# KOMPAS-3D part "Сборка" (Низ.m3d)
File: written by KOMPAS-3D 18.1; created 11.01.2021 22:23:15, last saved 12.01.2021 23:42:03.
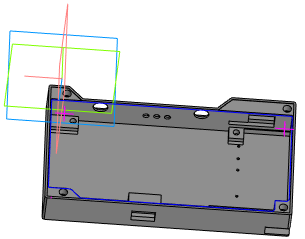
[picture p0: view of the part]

Document properties: Автор: DiSlord; Полное имя файла: Низ.m3d

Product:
- Part/product: Сборка
    Масса: 0.17294
  - Component [detail]: Деталь  | source file: Крышка экрана.m3d
  - Component [detail]: Низ  | source file: C:\Users\DiSlord\Documents\Низ.m3d

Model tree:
1. Эскиз:1  (with: Элемент выдавливания:1)
2. Элемент выдавливания:1
     Расстояние 1 = 17
3. Контур:1  (with: Элемент выдавливания:1)
     Радиус = 5
4. Элемент выдавливания:2  (with: Элемент выдавливания:1)
     Расстояние 2 = 15
5. Контур:2  (with: Элемент выдавливания:1)
     Радиус = 5
6. Элемент выдавливания:3  (with: Элемент выдавливания:1)
     Расстояние 2 = 15
7. Элемент выдавливания:4  (with: Элемент выдавливания:1)
     Расстояние 2 = 15
8. Элемент выдавливания:5  (with: Элемент выдавливания:1)
     Расстояние 2 = 15
9. Эскиз:2  (with: Элемент выдавливания:1)
10. Элемент выдавливания:6
     Расстояние 2 = 115
11. Эскиз:3  (with: Элемент выдавливания:1)
12. Элемент выдавливания:8
     Расстояние 2 = 17
13. Эскиз:4  (with: Элемент выдавливания:1, Элемент выдавливания:8)
14. Элемент выдавливания:9
     Расстояние 2 = 16
15. Эскиз:5  (with: Элемент выдавливания:9, Элемент выдавливания:1)
16. Эскиз:6  (with: Элемент выдавливания:1, Элемент выдавливания:9)
17. Элемент выдавливания:10  (with: Элемент выдавливания:1)
     Расстояние 1 = -17
18. Эскиз:7  (with: Элемент выдавливания:1, Элемент выдавливания:9, Элемент выдавливания:10)
19. Элемент выдавливания:11  (with: Элемент выдавливания:9)
     Расстояние 2 = 16
20. Эскиз:8  (with: Элемент выдавливания:9, Элемент выдавливания:11)
21. Элемент выдавливания:12
     Расстояние 1 = 0.01
22. Эскиз:9  (with: Элемент выдавливания:1, Элемент выдавливания:9)
23. Элемент выдавливания:13  (with: Элемент выдавливания:12)
     Расстояние 2 = 15.99
24. Эскиз:10  (with: Элемент выдавливания:12)
25. Элемент выдавливания:14
     Расстояние 2 = 1.01
26. Эскиз:11  (with: Элемент выдавливания:12)
27. Элемент выдавливания:17
     Расстояние 1 = 3.3
28. Эскиз:12  (with: Элемент выдавливания:1, Элемент выдавливания:14)
29. Элемент выдавливания:18
     Расстояние 2 = 17
30. Фаска:1  (with: Элемент выдавливания:14)
     Угол = 45; Длина 1 = 1.2; Длина 2 = 1.2
31. Фаска:2  (with: Элемент выдавливания:17)
     Угол = 45; Длина 1 = 1.2; Длина 2 = 1.2
32. Фаска:3  (with: Элемент выдавливания:17)
     Угол = 45; Длина 1 = 1.2; Длина 2 = 1.2
33. Эскиз:13  (with: Элемент выдавливания:9, Элемент выдавливания:12)
34. Элемент выдавливания:20  (with: Элемент выдавливания:17)
     Расстояние 1 = 3.31
35. Эскиз:14  (with: Элемент выдавливания:17, Элемент выдавливания:20)
36. Элемент выдавливания:21  (with: Элемент выдавливания:9)
     Расстояние 2 = 3.31
37. Элемент выдавливания:22  (with: Элемент выдавливания:12, Элемент выдавливания:9)
     Расстояние 2 = 0.01
38. Эскиз:15  (with: Элемент выдавливания:17)
39. Элемент выдавливания:23  (with: Элемент выдавливания:9)
     Расстояние 2 = 3.31
40. Фаска:5  (with: Элемент выдавливания:23)
     Угол = 45; Длина 1 = 1.2; Длина 2 = 1.2
41. Эскиз:16  (with: Элемент выдавливания:17, Элемент выдавливания:11)
42. Элемент выдавливания:24  (with: Элемент выдавливания:9)
     Расстояние 2 = 3.31
43. Фаска:6  (with: Элемент выдавливания:24)
     Угол = 45; Длина 1 = 1; Длина 2 = 1
44. Эскиз:17  (with: Элемент выдавливания:1)
45. Элемент выдавливания:25
     Расстояние 2 = 11.5
46. Эскиз:18  (with: Элемент выдавливания:1, Элемент выдавливания:25)
47. Элемент выдавливания:26
     Расстояние 2 = 90
48. Фаска:7  (with: Элемент выдавливания:9, Элемент выдавливания:21)
     Угол = 45; Длина 1 = 1; Длина 2 = 1
49. Эскиз:19  (with: Элемент выдавливания:1)
50. Элемент выдавливания:27
     Расстояние 2 = 4.2
51. Эскиз:20  (with: Элемент выдавливания:10, Элемент выдавливания:1)
52. Элемент выдавливания:28
     Расстояние 2 = 10
53. Эскиз:21  (with: Элемент выдавливания:10, Элемент выдавливания:28)
54. Элемент выдавливания:29
     Расстояние 2 = 10
55. Фаска:9  (with: Элемент выдавливания:9)
     Угол = 45; Длина 1 = 3; Длина 2 = 3
56. Фаска:10  (with: Элемент выдавливания:13)
     Угол = 45; Длина 1 = 3; Длина 2 = 3
57. Скругление:1  (with: Элемент выдавливания:13)
     Радиус = 3
58. Эскиз:22  (with: Элемент выдавливания:1)
59. Элемент выдавливания:31
     Расстояние 2 = 10
60. Скругление:2  (with: Элемент выдавливания:1, Элемент выдавливания:8, Элемент выдавливания:10)
     Радиус = 1
61. Эскиз:23  (with: Элемент выдавливания:17, Элемент выдавливания:11)
62. Элемент выдавливания:32  (with: Элемент выдавливания:9)
     Расстояние 2 = 3.31
63. Эскиз:24  (with: Элемент выдавливания:17)
64. Элемент выдавливания:33  (with: Элемент выдавливания:9)
     Расстояние 2 = 3.31
65. Эскиз:25  (with: Элемент выдавливания:17)
66. Элемент выдавливания:34  (with: Элемент выдавливания:9)
     Расстояние 2 = 3.31
67. Эскиз:26  (with: Элемент выдавливания:9, Элемент выдавливания:32)
68. Элемент выдавливания:36
     Расстояние 1 = 1
69. Эскиз:27  (with: Элемент выдавливания:17)
70. Элемент выдавливания:37  (with: Элемент выдавливания:9)
     Расстояние 2 = 3.31
71. Фаска:11  (with: Элемент выдавливания:34, Элемент выдавливания:32, Элемент выдавливания:37, Элемент выдавливания:11)
     Угол = 45; Длина 1 = 1; Длина 2 = 1
72. Эскиз:28  (with: Элемент выдавливания:11)
73. Элемент выдавливания:38
     Расстояние 2 = 7
74. Эскиз:29  (with: Элемент выдавливания:11, Элемент выдавливания:38)
75. Элемент выдавливания:39
     Расстояние 2 = 2.5
76. Эскиз:30  (with: Элемент выдавливания:38)
77. Элемент выдавливания:40
     Расстояние 2 = 10
78. Эскиз:31  (with: Элемент выдавливания:1)
79. Элемент выдавливания:41
     Расстояние 2 = 1.5
80. Эскиз:32  (with: Элемент выдавливания:10, Элемент выдавливания:29)
81. Элемент выдавливания:42  (with: Элемент выдавливания:11)
     Расстояние 1 = -1
82. Элемент выдавливания:43  (with: Элемент выдавливания:11)
     Расстояние 1 = -1
83. Эскиз:33  (with: Элемент выдавливания:11, Элемент выдавливания:29)
84. Элемент выдавливания:44
     Расстояние 2 = 10
85. Эскиз:34  (with: Элемент выдавливания:10, Элемент выдавливания:44)
86. Элемент выдавливания:45
     Расстояние 2 = 10
87. Эскиз:35  (with: Элемент выдавливания:1, Элемент выдавливания:10)
88. Элемент выдавливания:46
     Расстояние 2 = 15
89. Эскиз:36  (with: Элемент выдавливания:1, Элемент выдавливания:9, Элемент выдавливания:13)
90. Элемент выдавливания:47  (with: Элемент выдавливания:17)
91. Контур:4  (with: Элемент выдавливания:9, Элемент выдавливания:11, Фаска:7, Фаска:9, Скругление:1, Элемент выдавливания:13)
     Радиус = 5
92. Элемент выдавливания:48  (with: Элемент выдавливания:1)
     Расстояние 1 = 0.2
93. Эскиз:37  (with: Элемент выдавливания:17, Фаска:11)
94. Элемент выдавливания:49  (with: Элемент выдавливания:9)
     Расстояние 2 = 3.31
95. Эскиз:38  (with: Элемент выдавливания:17, Элемент выдавливания:18)
96. Элемент выдавливания:50
     Расстояние 2 = 10
97. Эскиз:40  (with: Элемент выдавливания:17, Элемент выдавливания:18)
98. Элемент выдавливания:51
     Расстояние 2 = 10
99. Эскиз:41  (with: Элемент выдавливания:1, Фаска:1)
100. Элемент выдавливания:52
     Расстояние 2 = 1.5
101. Эскиз:42  (with: Элемент выдавливания:52)
102. Элемент выдавливания:53
     Расстояние 2 = 10
103. Эскиз:43  (with: Элемент выдавливания:52)
104. Элемент выдавливания:54
105. Эскиз:44  (with: Элемент выдавливания:52)
106. Элемент выдавливания:55  (with: Элемент выдавливания:52)
     Расстояние 2 = 90
107. Фаска:12  (with: Элемент выдавливания:54, Элемент выдавливания:53)
     Угол = 45; Длина 1 = 1.2; Длина 2 = 1.2
108. Эскиз:45  (with: Элемент выдавливания:1, Элемент выдавливания:25)
109. Элемент выдавливания:56  (with: Элемент выдавливания:25)
     Расстояние 2 = 11.5
110. Эскиз:46  (with: Элемент выдавливания:1, Элемент выдавливания:48)
111. Эскиз:47  (with: Элемент выдавливания:48)
112. Элемент выдавливания:57  (with: Элемент выдавливания:17)
     Расстояние 2 = 12.89
113. Эскиз:48  (with: Элемент выдавливания:48)
114. Элемент выдавливания:59  (with: Элемент выдавливания:41)
     Расстояние 1 = -15.7
115. Эскиз:49  (with: Элемент выдавливания:57)
116. Элемент выдавливания:60
     Расстояние 2 = 10
117. Эскиз:50  (with: Элемент выдавливания:17, Элемент выдавливания:57, Фаска:11)
118. Элемент выдавливания:61  (with: Элемент выдавливания:9)
     Расстояние 2 = 3.31
119. Эскиз:51  (with: Элемент выдавливания:17, Фаска:11)
120. Элемент выдавливания:62  (with: Элемент выдавливания:9)
     Расстояние 2 = 3.31
121. Эскиз:52  (with: Элемент выдавливания:48)
122. Контур:5  (with: Элемент выдавливания:48, Элемент выдавливания:59)
     Радиус = 5
123. Контур:6
     Радиус = 5
124. Элемент выдавливания:63
     Расстояние 1 = 0.2
125. Эскиз:53  (with: Элемент выдавливания:25, Элемент выдавливания:56)
126. Элемент выдавливания:64  (with: Элемент выдавливания:26)
     Расстояние 2 = 78.5
127. Эскиз:54  (with: Элемент выдавливания:9, Элемент выдавливания:20, Элемент выдавливания:31, Элемент выдавливания:48)
128. Элемент выдавливания:65  (with: Элемент выдавливания:13)
     Расстояние 1 = 4.75
129. Эскиз:55  (with: Элемент выдавливания:25, Элемент выдавливания:56)
130. Элемент выдавливания:66  (with: Элемент выдавливания:26)
     Расстояние 2 = 78.5; Ориентация = 2

Referenced files in G:\: Крышка экрана.m3d
Referenced files in C:\Users\DiSlord\Documents\: Низ.m3d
